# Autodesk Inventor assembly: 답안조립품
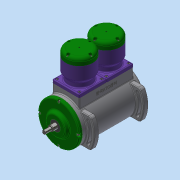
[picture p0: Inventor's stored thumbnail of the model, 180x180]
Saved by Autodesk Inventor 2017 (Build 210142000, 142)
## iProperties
Part Number: 답안조립품
Material: 일반
Document SubType Name: Assembly
Designer: Administrator
Author: Administrator
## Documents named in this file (16)
- C:\Users\Administrator\Desktop\620106V1009\답안조립품.iam
- C:\Users\Administrator\Desktop\620106V1009\본체.ipt
- C:\Users\Administrator\Desktop\620106V1009\실린더.ipt
- C:\Users\Administrator\Desktop\620106V1009\볼트 M4 x 12.ipt
- C:\Users\Administrator\Desktop\620106V1009\실린더헤드.ipt
- C:\Users\Administrator\Desktop\620106V1009\볼트 M5 x 20.ipt
- C:\Users\Administrator\Desktop\620106V1009\커넥팅로드 엔드.ipt
- C:\Users\Administrator\Desktop\620106V1009\커넥팅로드.ipt
- C:\Users\Administrator\Desktop\620106V1009\육각 머리 볼트 M4 x 16.ipt
- C:\Users\Administrator\Desktop\620106V1009\너트 M4.ipt
- C:\Users\Administrator\Desktop\620106V1009\피스톤.ipt
- C:\Users\Administrator\Desktop\620106V1009\피스톤핀.ipt
- C:\Users\Administrator\Desktop\620106V1009\베어링 6303.ipt
- C:\Users\Administrator\Desktop\620106V1009\크랭크축.ipt
- C:\Users\Administrator\Desktop\620106V1009\앞커버.ipt
- C:\Users\Administrator\Desktop\620106V1009\오일 실 17 x 32 x 8.ipt
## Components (4 placed, 2 different names)
1. 피스톤:1
2. 피스톤핀:1
3. 피스톤:2
4. 피스톤핀:2
## Named parameters: d38_d31 = 0, d39_d32 = 0, d40_d33 = 0, d41_d34 = 0, d42_d35 = 0, d43_d36 = 0, d44_d24 = 0, d45_d25 = 0, d46_d26 = 0, d47_d27 = 0, d48_d28 = 0, d49_d29 = 0, d50_d30 = 0
